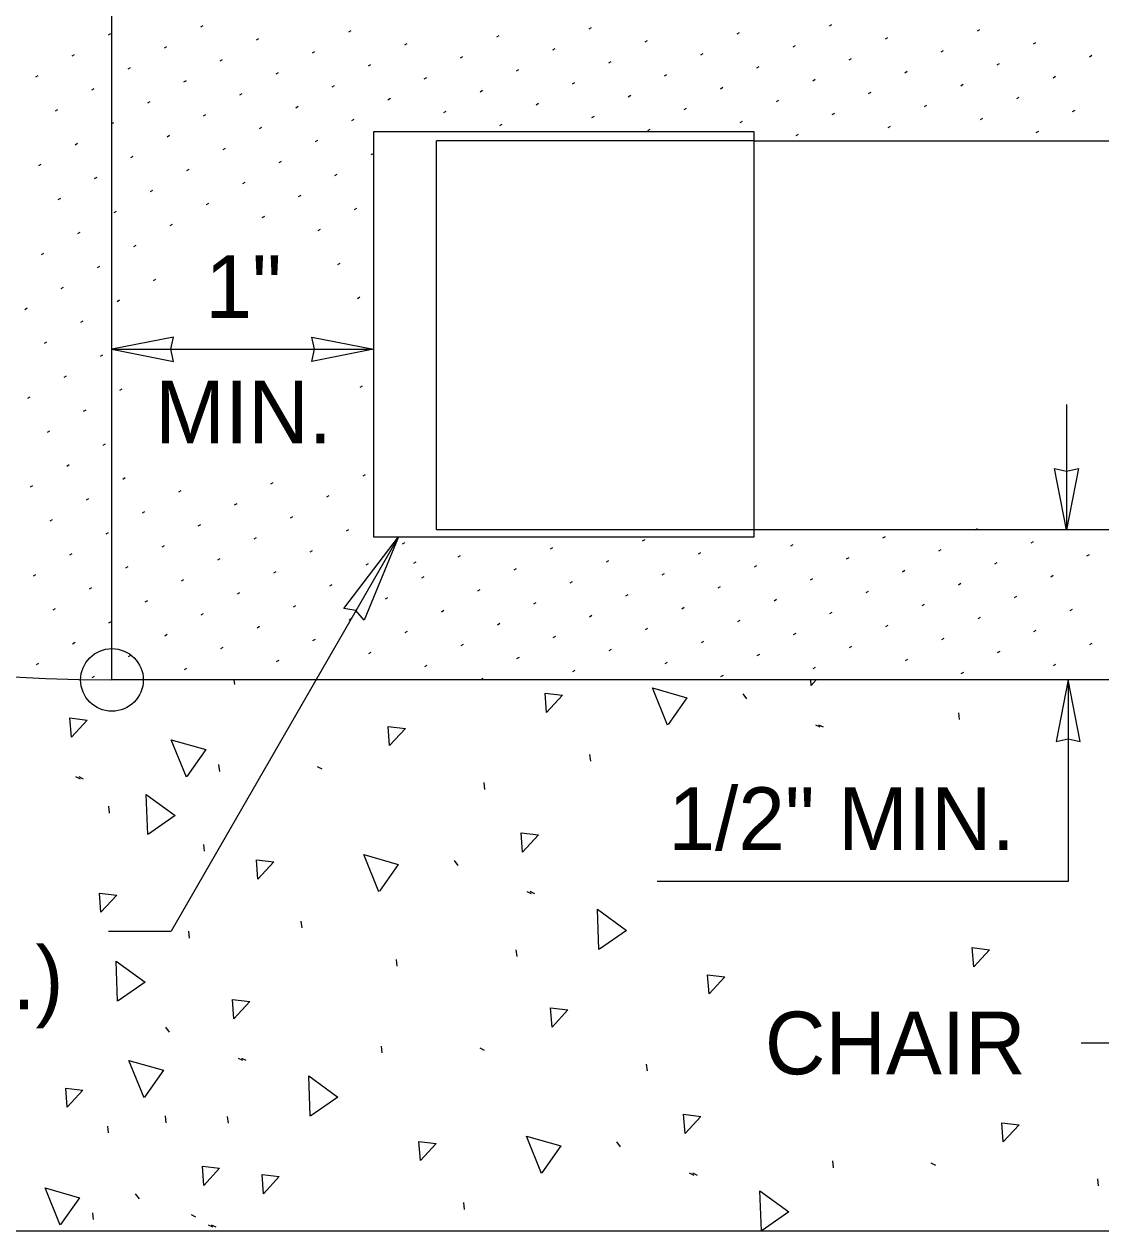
# Model space of a CAD drawing. Extents: x 99862 to 104211, y 98939 to 105076.
# Drawn here: x 100676.3 to 100951.2, y 103804.6 to 104112.6 of the extents above; entities that cross this region are included whole.
import ezdxf

# ---------------------------------------------------------------- set-up
doc = ezdxf.new("R2010")
doc.units = 0
for name, color, linetype in [('Level 1', 7, 'Continuous'), ('Level 15', 7, 'Continuous'), ('Level 2', 7, 'Continuous'), ('Level 20', 7, 'Continuous'), ('Level 3', 7, 'Continuous'), ('Level 4', 7, 'Continuous'), ('Level 6', 7, 'Continuous')]:
    doc.layers.add(name, color=color, linetype=linetype)

msp = doc.modelspace()

# ---------------------------------------------------------------- linework, layer by layer
at = {"layer": 'Level 1'}
msp.add_line((102063.85, 103945.23), (100698.76, 103945.23), dxfattribs=at)
msp.add_line((102063.85, 103945.23), (100698.76, 103945.23), dxfattribs=at)
msp.add_lwpolyline([(100169.63, 103804.62), (100694.77, 103804.62), (102647.84, 103804.62)], dxfattribs=at)
msp.add_ellipse((100698.76, 104535.63), major_axis=(0, -590.4), ratio=0.83118, start_param=5.208402, end_param=6.283185, dxfattribs=at)
msp.add_ellipse((100698.76, 104535.63), major_axis=(0, -590.4), ratio=0.83118, start_param=5.208402, end_param=6.283185, dxfattribs=at)
at = {"layer": 'Level 15'}
for p, q in [((100698.76, 103945.23), (100698.76, 104263.53)), ((100781.58, 103983.52), (100781.58, 104082.86)), ((100862.71, 104082.86), (100781.58, 104082.86)), ((100942.37, 104015.52), (100942.37, 103983.52)), ((100862.71, 103983.52), (100781.58, 103983.52)), ((100771.93, 103981.77), (100713.84, 103881.15)), ((100942.79, 103945.23), (100942.79, 103893.83)), ((100942.79, 103893.83), (100837.9, 103893.83)), ((100942.79, 103893.83), (100840.46, 103893.83)), ((100697.84, 103881.15), (100713.84, 103881.15)), ((100946.16, 103852.58), (100962.16, 103852.58))]:
    msp.add_line(p, q, dxfattribs=at)
for points in [[(100698.76, 104029.62), (100714.48, 104026.54), (100713.76, 104029.62), (100714.48, 104032.7)], [(100765.47, 104029.62), (100749.74, 104026.54), (100750.47, 104029.62), (100749.74, 104032.7)], [(100942.37, 103983.52), (100939.29, 103999.24), (100942.37, 103998.52), (100945.46, 103999.24)], [(100771.93, 103981.77), (100763.1, 103960.51), (100761.04, 103962.92), (100757.93, 103963.5)], [(100942.79, 103945.23), (100939.71, 103929.51), (100942.79, 103930.23), (100945.88, 103929.51)]]:
    msp.add_lwpolyline(points, close=True, dxfattribs=at)
msp.add_lwpolyline([(100698.76, 104029.62), (100765.47, 104029.62)], dxfattribs=at)
msp.add_circle((100698.76, 103945.23), 8, dxfattribs=at)
at = {"layer": 'Level 2'}
for p, q in [((100862.71, 104082.86), (101375.26, 104082.86)), ((100972, 103983.52), (100862.71, 103983.52))]:
    msp.add_line(p, q, dxfattribs=at)
at = {"layer": 'Level 20'}
msp.add_line((100765.47, 103983.77), (100765.47, 103983.77), dxfattribs=at)
at = {"layer": 'Level 3'}
for p, q in [((100721.4, 104111.92), (100722.01, 104112.27)), ((100820.54, 104111.42), (100821.15, 104111.77)), ((100881.88, 104112.19), (100882.49, 104112.54)), ((100697.87, 104109.87), (100698.47, 104110.22)), ((100735.67, 104108.61), (100736.27, 104108.96)), ((100759.2, 104110.65), (100759.81, 104111)), ((100797.01, 104109.38), (100797.61, 104109.73)), ((100858.35, 104110.15), (100858.95, 104110.5)), ((100896.15, 104108.88), (100896.75, 104109.23)), ((100919.68, 104110.92), (100920.29, 104111.27)), ((100712.13, 104106.57), (100712.74, 104106.92)), ((100749.94, 104105.3), (100750.54, 104105.65)), ((100773.47, 104107.34), (100774.08, 104107.69)), ((100811.27, 104106.07), (100811.88, 104106.42)), ((100834.81, 104108.11), (100835.42, 104108.46)), ((100872.61, 104106.84), (100873.22, 104107.19)), ((100910.42, 104105.57), (100911.02, 104105.92)), ((100933.95, 104107.61), (100934.56, 104107.96)), ((100688.6, 104104.52), (100689.2, 104104.87)), ((100726.4, 104103.26), (100727.01, 104103.61)), ((100787.74, 104104.03), (100788.35, 104104.38)), ((100825.54, 104102.76), (100826.15, 104103.11)), ((100849.08, 104104.8), (100849.68, 104105.15)), ((100886.88, 104103.53), (100887.49, 104103.88)), ((100924.68, 104102.26), (100925.29, 104102.61)), ((100948.22, 104104.31), (100948.83, 104104.66)), ((100679.33, 104099.17), (100679.94, 104099.52)), ((100702.87, 104101.21), (100703.47, 104101.56)), ((100740.67, 104099.95), (100741.27, 104100.3)), ((100764.2, 104101.99), (100764.81, 104102.34)), ((100802.01, 104100.72), (100802.61, 104101.07)), ((100839.81, 104099.45), (100840.42, 104099.8)), ((100863.35, 104101.49), (100863.95, 104101.84)), ((100901.15, 104100.22), (100901.75, 104100.57)), ((100938.95, 104098.95), (100939.56, 104099.3)), ((100693.6, 104095.86), (100694.2, 104096.21)), ((100717.13, 104097.9), (100717.74, 104098.25)), ((100754.94, 104096.64), (100755.54, 104096.99)), ((100778.47, 104098.68), (100779.08, 104099.03)), ((100816.27, 104097.41), (100816.88, 104097.76)), ((100854.08, 104096.14), (100854.68, 104096.49)), ((100877.61, 104098.18), (100878.22, 104098.53)), ((100915.42, 104096.91), (100916.02, 104097.26)), ((100731.4, 104094.6), (100732.01, 104094.95)), ((100769.2, 104093.33), (100769.81, 104093.68)), ((100792.74, 104095.37), (100793.35, 104095.72)), ((100830.54, 104094.1), (100831.15, 104094.45)), ((100868.35, 104092.83), (100868.95, 104093.18)), ((100891.88, 104094.87), (100892.49, 104095.22)), ((100929.68, 104093.6), (100930.29, 104093.95)), ((100684.33, 104090.51), (100684.94, 104090.86)), ((100707.87, 104092.55), (100708.47, 104092.9)), ((100745.67, 104091.29), (100746.27, 104091.64)), ((100783.47, 104090.02), (100784.08, 104090.37)), ((100807.01, 104092.06), (100807.61, 104092.41)), ((100844.81, 104090.79), (100845.42, 104091.14)), ((100906.15, 104091.56), (100906.75, 104091.91)), ((100943.95, 104090.29), (100944.56, 104090.64)), ((100698.6, 104087.2), (100699.2, 104087.55)), ((100722.13, 104089.24), (100722.74, 104089.59)), ((100759.94, 104087.98), (100760.54, 104088.33)), ((100797.74, 104086.71), (100798.35, 104087.06)), ((100821.27, 104088.75), (100821.88, 104089.1)), ((100859.08, 104087.48), (100859.68, 104087.83)), ((100882.61, 104089.52), (100883.22, 104089.87)), ((100920.42, 104088.25), (100921.02, 104088.6)), ((100712.87, 104083.89), (100713.47, 104084.24)), ((100736.4, 104085.94), (100737.01, 104086.29)), ((100835.54, 104085.44), (100836.15, 104085.79)), ((100873.35, 104084.17), (100873.95, 104084.52)), ((100896.88, 104086.21), (100897.49, 104086.56)), ((100934.68, 104084.94), (100935.29, 104085.29)), ((100689.33, 104081.85), (100689.94, 104082.2)), ((100727.13, 104080.58), (100727.74, 104080.93)), ((100750.67, 104082.63), (100751.27, 104082.98)), ((100703.6, 104078.54), (100704.2, 104078.89)), ((100764.94, 104079.32), (100765.47, 104079.62)), ((100680.06, 104076.5), (100680.67, 104076.85)), ((100717.87, 104075.23), (100718.47, 104075.58)), ((100741.4, 104077.27), (100742.01, 104077.62)), ((100694.33, 104073.19), (100694.94, 104073.54)), ((100732.13, 104071.92), (100732.74, 104072.27)), ((100755.67, 104073.97), (100756.27, 104074.32)), ((100708.6, 104069.88), (100709.2, 104070.23)), ((100746.4, 104068.61), (100747.01, 104068.96)), ((100685.06, 104067.84), (100685.67, 104068.19)), ((100722.87, 104066.57), (100723.47, 104066.92)), ((100760.67, 104065.31), (100761.27, 104065.66)), ((100699.33, 104064.53), (100699.94, 104064.88)), ((100737.13, 104063.26), (100737.74, 104063.61)), ((100690.06, 104059.18), (100690.67, 104059.53)), ((100713.6, 104061.22), (100714.2, 104061.57)), ((100751.4, 104059.95), (100752.01, 104060.3)), ((100704.33, 104055.87), (100704.94, 104056.22)), ((100680.79, 104053.83), (100681.4, 104054.18)), ((100695.06, 104050.52), (100695.67, 104050.87)), ((100756.4, 104051.29), (100757.01, 104051.64)), ((100709.33, 104047.21), (100709.94, 104047.56)), ((100685.79, 104045.17), (100686.4, 104045.52)), ((100700.06, 104041.86), (100700.67, 104042.21)), ((100761.4, 104042.63), (100762.01, 104042.98)), ((100676.53, 104039.82), (100677.13, 104040.17)), ((100690.79, 104036.51), (100691.4, 104036.86)), ((100681.53, 104031.16), (100682.13, 104031.51)), ((100695.79, 104027.85), (100696.4, 104028.2)), ((100686.53, 104022.5), (100687.13, 104022.85)), ((100700.79, 104019.19), (100701.4, 104019.54)), ((100762.13, 104019.96), (100762.74, 104020.31)), ((100677.26, 104017.15), (100677.87, 104017.5)), ((100691.53, 104013.84), (100692.13, 104014.19)), ((100682.26, 104008.49), (100682.87, 104008.84)), ((100696.53, 104005.18), (100697.13, 104005.53)), ((100687.26, 103999.83), (100687.87, 104000.18)), ((100762.87, 103997.29), (100763.47, 103997.64)), ((100677.99, 103994.48), (100678.6, 103994.83)), ((100701.53, 103996.52), (100702.13, 103996.87)), ((100739.33, 103995.25), (100739.94, 103995.6)), ((100692.26, 103991.17), (100692.87, 103991.52)), ((100715.79, 103993.21), (100716.4, 103993.56)), ((100753.6, 103991.94), (100754.2, 103992.29)), ((100730.06, 103989.9), (100730.67, 103990.25)), ((100682.99, 103985.82), (100683.6, 103986.17)), ((100706.53, 103987.86), (100707.13, 103988.21)), ((100744.33, 103986.59), (100744.94, 103986.94)), ((100697.26, 103982.51), (100697.87, 103982.86)), ((100720.79, 103984.55), (100721.4, 103984.9)), ((100758.6, 103983.28), (100759.2, 103983.63)), ((100919.08, 103983.56), (100919.68, 103983.91)), ((100711.53, 103979.2), (100712.13, 103979.55)), ((100735.06, 103981.24), (100735.67, 103981.59)), ((100772.87, 103979.97), (100773.47, 103980.32)), ((100834.2, 103980.74), (100834.81, 103981.09)), ((100872.01, 103979.48), (100872.61, 103979.83)), ((100895.54, 103981.52), (100896.15, 103981.87)), ((100933.35, 103980.25), (100933.95, 103980.6)), ((100687.99, 103977.16), (100688.6, 103977.51)), ((100725.79, 103975.89), (100726.4, 103976.24)), ((100749.33, 103977.93), (100749.94, 103978.28)), ((100787.13, 103976.66), (100787.74, 103977.01)), ((100810.67, 103978.7), (100811.27, 103979.05)), ((100848.47, 103977.43), (100849.08, 103977.78)), ((100886.27, 103976.17), (100886.88, 103976.52)), ((100909.81, 103978.21), (100910.42, 103978.56)), ((100947.61, 103976.94), (100948.22, 103977.29)), ((100702.26, 103973.85), (100702.87, 103974.2)), ((100763.6, 103974.62), (100764.2, 103974.97)), ((100775.79, 103975.05), (100776.4, 103975.4)), ((100801.4, 103973.35), (100802.01, 103973.7)), ((100824.94, 103975.39), (100825.54, 103975.74)), ((100862.74, 103974.12), (100863.35, 103974.47)), ((100900.54, 103972.86), (100901.15, 103973.21)), ((100924.08, 103974.9), (100924.68, 103975.25)), ((100678.72, 103971.81), (100679.33, 103972.16)), ((100716.53, 103970.54), (100717.13, 103970.89)), ((100740.06, 103972.58), (100740.67, 103972.93)), ((100777.87, 103971.31), (100778.47, 103971.66)), ((100815.67, 103970.04), (100816.27, 103970.39)), ((100839.2, 103972.08), (100839.81, 103972.43)), ((100877.01, 103970.81), (100877.61, 103971.16)), ((100938.35, 103971.59), (100938.95, 103971.94)), ((100692.99, 103968.5), (100693.6, 103968.85)), ((100730.79, 103967.23), (100731.4, 103967.58)), ((100754.33, 103969.27), (100754.94, 103969.62)), ((100792.13, 103968), (100792.74, 103968.35)), ((100829.94, 103966.73), (100830.54, 103967.08)), ((100853.47, 103968.77), (100854.08, 103969.12)), ((100891.27, 103967.51), (100891.88, 103967.86)), ((100914.81, 103969.55), (100915.42, 103969.9)), ((100707.26, 103965.19), (100707.87, 103965.54)), ((100745.06, 103963.92), (100745.67, 103964.27)), ((100768.6, 103965.96), (100769.2, 103966.31)), ((100806.4, 103964.69), (100807.01, 103965.04)), ((100844.2, 103963.42), (100844.81, 103963.77)), ((100867.74, 103965.46), (100868.35, 103965.81)), ((100905.54, 103964.2), (100906.15, 103964.55)), ((100929.08, 103966.24), (100929.68, 103966.59)), ((100683.72, 103963.15), (100684.33, 103963.5)), ((100721.53, 103961.88), (100722.13, 103962.23)), ((100759.33, 103960.61), (100759.94, 103960.96)), ((100782.87, 103962.65), (100783.47, 103963)), ((100820.67, 103961.38), (100821.27, 103961.73)), ((100882.01, 103962.15), (100882.61, 103962.5)), ((100919.81, 103960.89), (100920.42, 103961.24)), ((100943.35, 103962.93), (100943.95, 103963.28)), ((100697.99, 103959.84), (100698.6, 103960.19)), ((100735.79, 103958.57), (100736.4, 103958.92)), ((100773.6, 103957.3), (100774.2, 103957.65)), ((100797.13, 103959.34), (100797.74, 103959.69)), ((100834.94, 103958.07), (100835.54, 103958.42)), ((100858.47, 103960.11), (100859.08, 103960.46)), ((100896.27, 103958.85), (100896.88, 103959.2)), ((100934.08, 103957.58), (100934.68, 103957.93)), ((100688.72, 103954.49), (100689.33, 103954.84)), ((100712.26, 103956.53), (100712.87, 103956.88)), ((100750.06, 103955.26), (100750.67, 103955.61)), ((100811.4, 103956.03), (100812.01, 103956.38)), ((100849.2, 103954.76), (100849.81, 103955.11)), ((100872.74, 103956.8), (100873.35, 103957.15)), ((100910.54, 103955.54), (100911.15, 103955.89)), ((100948.35, 103954.27), (100948.95, 103954.62)), ((100702.99, 103951.18), (100703.6, 103951.53)), ((100726.53, 103953.22), (100727.13, 103953.57)), ((100764.33, 103951.95), (100764.94, 103952.3)), ((100787.87, 103953.99), (100788.47, 103954.34)), ((100825.67, 103952.72), (100826.27, 103953.07)), ((100863.47, 103951.45), (100864.08, 103951.8)), ((100887.01, 103953.49), (100887.61, 103953.84)), ((100924.81, 103952.23), (100925.42, 103952.58)), ((100679.46, 103949.14), (100680.06, 103949.49)), ((100740.79, 103949.91), (100741.4, 103950.26)), ((100778.6, 103948.64), (100779.2, 103948.99)), ((100802.13, 103950.68), (100802.74, 103951.03)), ((100839.94, 103949.41), (100840.54, 103949.76)), ((100877.74, 103948.14), (100878.35, 103948.49)), ((100901.27, 103950.18), (100901.88, 103950.53)), ((100939.08, 103948.92), (100939.68, 103949.27)), ((100693.72, 103945.83), (100694.33, 103946.18)), ((100717.26, 103947.87), (100717.87, 103948.22)), ((100792.87, 103945.33), (100793.47, 103945.68)), ((100816.4, 103947.37), (100817.01, 103947.72)), ((100854.2, 103946.1), (100854.81, 103946.45)), ((100915.54, 103946.88), (100916.15, 103947.23))]:
    msp.add_line(p, q, dxfattribs=at)
at = {"layer": 'Level 4'}
for p, q in [((100730.08, 103944.03), (100729.96, 103945.23)), ((100859.74, 103941.73), (100860.7, 103940.43)), ((100915.09, 103935.12), (100914.9, 103936.86)), ((100878.31, 103933.81), (100879.46, 103933.24)), ((100879.13, 103933.81), (100880.28, 103933.25)), ((100820.94, 103924.48), (100820.76, 103926.22)), ((100726.25, 103921.9), (100726.07, 103923.63)), ((100751.16, 103923.15), (100752.31, 103922.58)), ((100689.48, 103920.58), (100690.62, 103920.01)), ((100690.29, 103920.59), (100691.44, 103920.02)), ((100793.92, 103917.29), (100793.74, 103919.03)), ((100698.11, 103911.25), (100697.92, 103912.99)), ((100722.41, 103901.49), (100722.22, 103903.23)), ((100786.07, 103899.19), (100787.02, 103897.89)), ((100804.63, 103891.27), (100805.78, 103890.7)), ((100805.45, 103891.28), (100806.6, 103890.71)), ((100747.27, 103881.94), (100747.08, 103883.68)), ((100718.57, 103879.36), (100718.39, 103881.1)), ((100802.14, 103874.63), (100801.96, 103876.37)), ((100771.56, 103872.18), (100771.38, 103873.92)), ((100712.39, 103856.65), (100713.34, 103855.36)), ((100767.73, 103850.05), (100767.55, 103851.79)), ((100792.64, 103851.3), (100793.79, 103850.74)), ((100730.96, 103848.73), (100732.11, 103848.17)), ((100731.78, 103848.74), (100732.92, 103848.17)), ((100835.41, 103845.44), (100835.22, 103847.18)), ((100697.89, 103829.64), (100697.7, 103831.38)), ((100712.57, 103832.21), (100712.39, 103833.95)), ((100728.46, 103832.09), (100728.28, 103833.83)), ((100827.55, 103827.34), (100828.5, 103826.05)), ((100882.89, 103820.74), (100882.71, 103822.48)), ((100846.12, 103819.42), (100847.26, 103818.86)), ((100846.93, 103819.43), (100848.08, 103818.86)), ((100907.8, 103821.99), (100908.95, 103821.43)), ((100950.56, 103816.13), (100950.38, 103817.87)), ((100704.71, 103814.11), (100705.66, 103812.82)), ((100788.75, 103810.09), (100788.56, 103811.83)), ((100694.05, 103807.51), (100693.87, 103809.25)), ((100718.96, 103808.77), (100720.11, 103808.2)), ((100723.28, 103806.2), (100724.43, 103805.63)), ((100724.1, 103806.2), (100725.25, 103805.63)), ((100761.55, 103804.62), (100761.54, 103804.64))]:
    msp.add_line(p, q, dxfattribs=at)
for points in [[(100840.58, 103933.69), (100836.72, 103943.18), (100845.51, 103940.68), (100840.69, 103933.82)], [(100877.23, 103943.85), (100877.13, 103945.23)], [(100878.51, 103945.23), (100877.23, 103943.85)], [(100809.68, 103936.95), (100809.31, 103941.86), (100813.72, 103941.33), (100809.68, 103936.95)], [(100688.4, 103930.62), (100688.02, 103935.53), (100692.43, 103935), (100688.4, 103930.62)], [(100769.62, 103928.48), (100769.24, 103933.39), (100773.65, 103932.86), (100769.62, 103928.48)], [(100717.74, 103920.46), (100713.88, 103929.96), (100722.68, 103927.45), (100717.85, 103920.6)], [(100707.88, 103905.75), (100707.51, 103916), (100714.91, 103910.63), (100708.04, 103905.84)], [(100803.56, 103901.31), (100803.18, 103906.22), (100807.59, 103905.69), (100803.56, 103901.31)], [(100736.01, 103894.41), (100735.63, 103899.32), (100740.04, 103898.79), (100736.01, 103894.41)], [(100766.9, 103891.15), (100763.04, 103900.65), (100771.83, 103898.14), (100767.01, 103891.29)], [(100695.94, 103885.94), (100695.57, 103890.85), (100699.97, 103890.32), (100695.94, 103885.94)], [(100823.04, 103876.44), (100822.67, 103886.69), (100830.07, 103881.32), (100823.2, 103876.53)], [(100918.72, 103872), (100918.34, 103876.91), (100922.75, 103876.38), (100918.72, 103872)], [(100700.21, 103863.22), (100699.83, 103873.46), (100707.23, 103868.09), (100700.36, 103863.31)], [(100851.16, 103865.1), (100850.79, 103870.01), (100855.2, 103869.48), (100851.16, 103865.1)], [(100729.88, 103858.78), (100729.5, 103863.69), (100733.91, 103863.16), (100729.88, 103858.78)], [(100811.1, 103856.63), (100810.72, 103861.54), (100815.13, 103861.01), (100811.1, 103856.63)], [(100706.95, 103838.61), (100703.09, 103848.11), (100711.88, 103845.6), (100707.06, 103838.75)], [(100749.36, 103833.91), (100748.99, 103844.15), (100756.39, 103838.78), (100749.52, 103834)], [(100687.33, 103836.17), (100686.95, 103841.08), (100691.36, 103840.55), (100687.33, 103836.17)], [(100845.04, 103829.47), (100844.66, 103834.38), (100849.07, 103833.84), (100845.04, 103829.47)], [(100926.26, 103827.32), (100925.88, 103832.23), (100930.29, 103831.7), (100926.26, 103827.32)], [(100808.38, 103819.3), (100804.52, 103828.8), (100813.32, 103826.29), (100808.49, 103819.44)], [(100777.49, 103822.56), (100777.11, 103827.47), (100781.52, 103826.94), (100777.49, 103822.56)], [(100722.2, 103816.24), (100721.83, 103821.15), (100726.24, 103820.62), (100722.2, 103816.24)], [(100737.42, 103814.09), (100737.05, 103819), (100741.46, 103818.47), (100737.42, 103814.09)], [(100685.54, 103806.08), (100681.69, 103815.57), (100690.48, 103813.06), (100685.66, 103806.21)], [(100864.52, 103804.62), (100864.15, 103814.84), (100871.55, 103809.47), (100864.68, 103804.68)]]:
    msp.add_lwpolyline(points, dxfattribs=at)
at = {"layer": 'Level 6'}
for p, q in [((100862.71, 104085.12), (100765.47, 104085.12)), ((100765.47, 104085.12), (100765.47, 103981.77)), ((100862.71, 103981.77), (100862.71, 104085.12)), ((100765.47, 103981.77), (100862.71, 103981.77))]:
    msp.add_line(p, q, dxfattribs=at)

# ---------------------------------------------------------------- texts
at = {"layer": 'Level 20'}
for s, p in [('1"', (100722.6, 104037.62)), ('MIN.', (100709.78, 104005.62)), ('1/2" MIN.', (100840.78, 103901.83)), ('(TYP.)', (100624.57, 103861.15)), ('CHAIR', (100865.4, 103844.58))]:
    msp.add_text(s, height=16, dxfattribs=at).set_placement(p)

doc.saveas('drawing.dxf')
